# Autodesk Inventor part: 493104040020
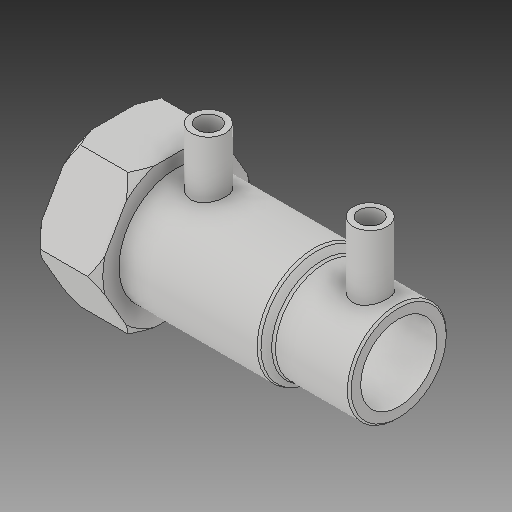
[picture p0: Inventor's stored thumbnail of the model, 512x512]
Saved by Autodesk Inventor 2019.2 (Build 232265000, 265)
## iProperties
Created: 2021-03
Part Number: 493104040020
Material: Generic
Description: Plasson Female Transition Reducer 40 x 2"
Document SubType Name: Modeling
Designer: Lenora
Categories: <MemberInstance><Categories><Category DisplayName="" InternalName="4347fa0f-2144-441d-94cd-e3e15c92b736" Mnemonic="TUBEANDPIPE"><CategoryParameter DisplayName="
Density: 1 g/cm^3
Appearance: Default
Author: Lenora
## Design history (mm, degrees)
derived "493104-R.ipt"
feature "Solid1::493104-R.ipt"
tag "TaggingFeature1"
body "Solid1"
other parameters: "d1" = 56.656, "d3" = 44, "d4" = 33, "d5" = 48, "d6" = 26.4, "d7" = 84.984, "d8" = 52, "d10" = 45 deg, "d11" = 39.6, "d13" = 59, "d14" = 18, "d15" = 12, "d16" = 1, "d17" = 17.7, "d18" = 1, "d19" = 17.7, "d20" = 12, "d21" = 18, "d22" = 59, "d23" = 15, "d28" = 0, "d30" = 0, "d31" = 4, "d35" = 0, "d36" = 2, "d37" = 1, "Rp" = 56.656, "L1" = 44, "L2" = 33, "D" = 48, "A_" = 59
